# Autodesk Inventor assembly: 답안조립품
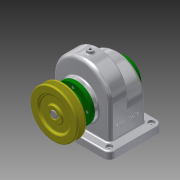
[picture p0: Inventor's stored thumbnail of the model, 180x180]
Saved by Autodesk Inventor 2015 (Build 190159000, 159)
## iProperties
Created: 2017-11
Part Number: 답안조립품
Document SubType Name: Assembly
Designer: 2-PC07
Author: 2-PC07
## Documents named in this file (14)
- C:\Users\2-PC07\Desktop\471108V1022\답안조립품.iam
- C:\Users\2-PC07\Desktop\471108V1022\본체.ipt
- C:\Users\2-PC07\Desktop\471108V1022\뒤커버.ipt
- C:\Users\2-PC07\Desktop\471108V1022\앞커버.ipt
- C:\Users\2-PC07\Desktop\471108V1022\베어링 6002.ipt
- C:\Users\2-PC07\Desktop\471108V1022\축.ipt
- C:\Users\2-PC07\Desktop\471108V1022\키 - 6 x 6 x 22.ipt
- C:\Users\2-PC07\Desktop\471108V1022\키 - 5 x 5 x 18.ipt
- C:\Users\2-PC07\Desktop\471108V1022\오일 실 15 30 7.ipt
- C:\Users\2-PC07\Desktop\471108V1022\스퍼기어.ipt
- C:\Users\2-PC07\Desktop\471108V1022\V-벨트풀리.ipt
- C:\Users\2-PC07\Desktop\471108V1022\멈춤나사 - M4 x 10.ipt
- 멈춤나사 - M4 x 10.ipt
- C:\Users\2-PC07\Desktop\471108V1022\볼트 M3 x 8.ipt
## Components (1 placed, 1 different names)
1. V-벨트풀리:1 — 각도:2
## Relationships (1: Angle 1)
- 각도:2 [Angle]: V-벨트풀리:1
